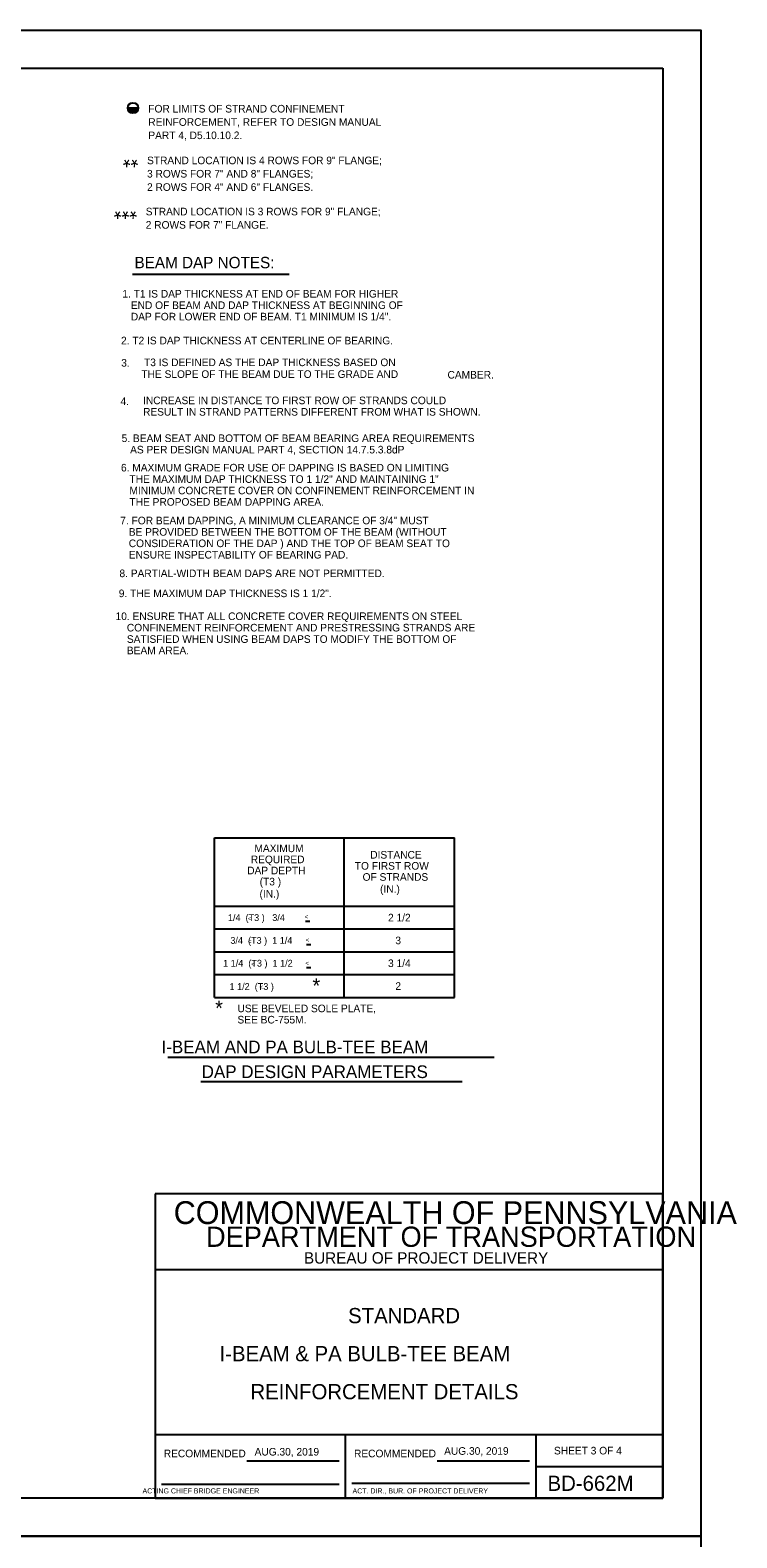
# Model space of a CAD drawing. Extents: x 637933 to 640019, y 298854 to 300042.
# Drawn here: x 639402 to 639680, y 299447 to 300042 of the extents above; entities that cross this region are included whole.
import ezdxf

# ---------------------------------------------------------------- set-up
doc = ezdxf.new("R2010")
doc.units = 0
doc.layers.add('1', color=7, linetype='Continuous')
doc.layers.add('PLT-BNDY', color=7, linetype='Continuous')

msp = doc.modelspace()

# ---------------------------------------------------------------- linework, layer by layer
at = {"layer": '1'}
for p, q in [((638864.93, 300027.12), (639650.94, 300027.12)), ((639650.94, 300027.12), (639650.94, 299463.12)), ((639440.07, 300011.42), (639444.2, 300011.42)), ((639442, 299945.9), (639503.75, 299945.9)), ((639474.3, 299723.61), (639568.92, 299723.61)), ((639474.3, 299660.61), (639474.3, 299723.61)), ((639525.42, 299696.61), (639525.42, 299723.61)), ((639568.92, 299696.61), (639568.92, 299723.61)), ((639474.3, 299696.61), (639568.92, 299696.61)), ((639525.42, 299660.61), (639525.42, 299696.61)), ((639568.92, 299660.61), (639568.92, 299696.61)), ((639474.3, 299687.61), (639568.92, 299687.61)), ((639511.86, 299690.52), (639510.17, 299690.52)), ((639512.22, 299681.35), (639510.54, 299681.35)), ((639474.3, 299678.61), (639568.92, 299678.61)), ((639474.3, 299669.61), (639568.92, 299669.61)), ((639510.51, 299672.37), (639512.19, 299672.37)), ((639474.3, 299660.61), (639568.92, 299660.61)), ((639584.48, 299636.91), (639455.84, 299636.91)), ((639571.85, 299627.29), (639468.91, 299627.29)), ((639650.94, 299583.12), (639450.94, 299583.12)), ((639450.94, 299583.12), (639450.94, 299463.12)), ((639650.94, 299463.12), (639650.94, 299583.12)), ((639650.94, 299553.12), (639450.94, 299553.12)), ((639650.94, 299488.12), (639450.94, 299488.12)), ((639525.94, 299463.12), (639525.94, 299488.12)), ((639600.94, 299488.12), (639600.94, 299463.12)), ((639487.02, 299477.83), (639523.44, 299477.83)), ((639562.02, 299477.83), (639598.44, 299477.83)), ((639600.94, 299475.62), (639650.94, 299475.62)), ((639453.44, 299468.62), (639523.44, 299468.62)), ((639528.44, 299468.99), (639598.44, 299468.99)), ((639650.94, 299463.12), (638864.93, 299463.12)), ((639450.94, 299463.12), (639650.94, 299463.12))]:
    msp.add_line(p, q, dxfattribs=at)
msp.add_circle((639442.14, 300011.42), 2.07, dxfattribs=at)
for radius in [1.94, 1.81, 1.68, 1.55, 1.42, 1.29, 1.16, 1.03, 0.905, 0.775, 0.646, 0.517, 0.388, 0.258, 0.129]:
    msp.add_arc((639442.14, 300011.42), radius, 180, 0, dxfattribs=at)
at = {"layer": 'PLT-BNDY'}
for points in [[(638824.93, 300042.12), (639665.93, 300042.12), (639665.93, 299448.12), (638824.93, 299448.12)], [(638824.93, 299448.12), (639665.93, 299448.12), (639665.93, 298854.12), (638824.93, 298854.12)]]:
    msp.add_lwpolyline(points, close=True, dxfattribs=at)

# ---------------------------------------------------------------- texts
at = {"layer": '1'}
for s, height, p in [('FOR LIMITS OF STRAND CONFINEMENT', 3, (639448.19, 300009.64)), ('REINFORCEMENT, REFER TO DESIGN MANUAL', 3, (639448.19, 300004.39)), ('PART 4, D5.10.10.2.', 3, (639448.19, 299999.14)), ('STRAND LOCATION IS 4 ROWS FOR 9" FLANGE;', 3, (639447.68, 299989.24)), ('3 ROWS FOR 7" AND 8" FLANGES;', 3, (639447.68, 299983.99)), ('2 ROWS FOR 4" AND 6" FLANGES.', 3, (639447.68, 299978.74)), ('STRAND LOCATION IS 3 ROWS FOR 9" FLANGE;', 3, (639447.17, 299969.07)), ('2 ROWS FOR 7" FLANGE.', 3, (639447.17, 299963.82)), ('BEAM DAP NOTES:', 4.5, (639442.74, 299948.21)), ('1. T1 IS DAP THICKNESS AT END OF BEAM FOR HIGHER', 3, (639437.95, 299936.64)), ('   END OF BEAM AND DAP THICKNESS AT BEGINNING OF', 3, (639437.95, 299932.14)), ('   DAP FOR LOWER END OF BEAM. T1 MINIMUM IS 1/4".', 3, (639437.95, 299927.64)), ('2. T2 IS DAP THICKNESS AT CENTERLINE OF BEARING.', 3, (639437.43, 299918.19)), ('T3 IS DEFINED AS THE DAP THICKNESS BASED ON', 3, (639446.49, 299909.6)), ('THE SLOPE OF THE BEAM DUE TO THE GRADE AND', 3, (639445.46, 299904.96)), ('    CAMBER.', 3, (639561.67, 299904.69)), ('INCREASE IN DISTANCE TO FIRST ROW OF STRANDS COULD', 3, (639446.11, 299894.59)), ('RESULT IN STRAND PATTERNS DIFFERENT FROM WHAT IS SHOWN.', 3, (639446.11, 299890.09)), ('5. BEAM SEAT AND BOTTOM OF BEAM BEARING AREA REQUIREMENTS', 3, (639437.67, 299879.67)), ('   AS PER DESIGN MANUAL PART 4, SECTION 14.7.5.3.8dP', 3, (639437.67, 299875.17)), ('6. MAXIMUM GRADE FOR USE OF DAPPING IS BASED ON LIMITING', 3, (639437.41, 299868.06)), ('   THE MAXIMUM DAP THICKNESS TO 1 1/2" AND MAINTAINING 1"', 3, (639437.41, 299863.56)), ('   MINIMUM CONCRETE COVER ON CONFINEMENT REINFORCEMENT IN', 3, (639437.41, 299859.06)), ('   THE PROPOSED BEAM DAPPING AREA.', 3, (639437.41, 299854.56)), ('7. FOR BEAM DAPPING, A MINIMUM CLEARANCE OF 3/4" MUST', 3, (639437.13, 299847.22)), ('   BE PROVIDED BETWEEN THE BOTTOM OF THE BEAM (WITHOUT', 3, (639437.13, 299842.72)), ('   CONSIDERATION OF THE DAP ) AND THE TOP OF BEAM SEAT TO', 3, (639437.13, 299838.22)), ('   ENSURE INSPECTABILITY OF BEARING PAD.', 3, (639437.13, 299833.72)), ('8. PARTIAL-WIDTH BEAM DAPS ARE NOT PERMITTED.', 3, (639436.81, 299826.38)), ('9. THE MAXIMUM DAP THICKNESS IS 1 1/2".', 3, (639436.55, 299818.49)), ('10. ENSURE THAT ALL CONCRETE COVER REQUIREMENTS ON STEEL', 3, (639435.27, 299809.46)), ('    CONFINEMENT REINFORCEMENT AND PRESTRESSING STRANDS ARE', 3, (639435.27, 299804.96)), ('    SATISFIED WHEN USING BEAM DAPS TO MODIFY THE BOTTOM OF', 3, (639435.27, 299800.46)), ('    BEAM AREA.', 3, (639435.27, 299795.96)), ('MAXIMUM', 3, (639490.01, 299717.93)), ('REQUIRED', 3, (639488.58, 299713.55)), ('DISTANCE', 3, (639535.66, 299715.38)), ('DAP DEPTH', 3, (639487.16, 299709.18)), ('TO FIRST ROW', 3, (639529.58, 299711.01)), ('OF STRANDS', 3, (639532.66, 299706.63)), ('(IN.)', 3, (639492.02, 299700.02)), ('(T3 )', 3, (639492.08, 299704.8)), ('(IN.)', 3, (639539.54, 299701.89)), ('1/4  (T3 )   3/4', 2.673, (639479.57, 299690.77)), ('<', 1.75, (639487.44, 299690.85)), ('<', 1.75, (639509.79, 299691.59)), ('2 1/2', 3, (639542.68, 299690.6)), ('3/4  (T3 )  1 1/4', 2.673, (639480.53, 299681.77)), ('<', 1.75, (639487.45, 299681.85)), ('<', 1.75, (639510.28, 299682.42)), ('3', 3, (639545.57, 299681.6)), ('1 1/4  (T3 )  1 1/2', 2.673, (639477.68, 299672.77)), ('<', 1.75, (639488.75, 299672.85)), ('<', 1.75, (639510.09, 299673.25)), ('3 1/4', 3, (639542.68, 299672.6)), ('*', 5.88, (639512.89, 299662.31)), ('1 1/2  (T3 )  ', 2.673, (639480.2, 299663.58)), ('<', 1.75, (639491.97, 299663.85)), ('2', 3, (639545.57, 299663.6)), ('*', 5.88, (639474.53, 299653.48)), ('USE BEVELED SOLE PLATE,', 3, (639483.32, 299654.78)), ('SEE BC-755M.', 3, (639483.32, 299650.34)), ('I-BEAM AND PA BULB-TEE BEAM', 5, (639453.41, 299638.58)), ('DAP DESIGN PARAMETERS', 5, (639469.22, 299628.82)), ('COMMONWEALTH OF PENNSYLVANIA', 9, (639458.19, 299571.24)), ('DEPARTMENT OF TRANSPORTATION', 8.0003, (639470.94, 299562.24)), ('BUREAU OF PROJECT DELIVERY', 4.5, (639509.53, 299555.62)), ('STANDARD', 6, (639526.94, 299532.12)), ('I-BEAM & PA BULB-TEE BEAM', 6, (639476.26, 299517.12)), ('REINFORCEMENT DETAILS', 6, (639488.44, 299502.12)), ('AUG.30, 2019', 3, (639564.79, 299480.23)), ('SHEET 3 OF 4', 3, (639608.09, 299480.37)), ('RECOMMENDED', 3, (639454.27, 299479.24)), ('AUG.30, 2019', 3, (639490.08, 299479.93)), ('RECOMMENDED', 3, (639529.27, 299479.24)), ('BD-662M', 6, (639605.56, 299465.99)), ('       ACTING CHIEF BRIDGE ENGINEER', 2.0002, (639440.52, 299464.99)), ('ACT. DIR., BUR. OF PROJECT DELIVERY', 2.0002, (639528.69, 299464.99))]:
    msp.add_text(s, height=height, dxfattribs=at).set_placement(p)
for s, height, rotation, p in [('**', 5.88, 180, (639444.25, 299993.95)), ('***', 5.88, 180, (639443.74, 299973.55)), ('3.', 3, 359, (639437.48, 299909.43)), ('4.', 3, 359, (639437.21, 299894.28))]:
    msp.add_text(s, height=height, rotation=rotation, dxfattribs=at).set_placement(p)

doc.saveas('drawing.dxf')
